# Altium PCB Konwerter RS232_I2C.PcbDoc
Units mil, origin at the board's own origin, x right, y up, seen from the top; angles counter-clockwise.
Board outline 6000 x 4000 mil, 2 copper layers (Top Layer, Bottom Layer); 20 components, 24 nets, 88 pads, 18 vias.
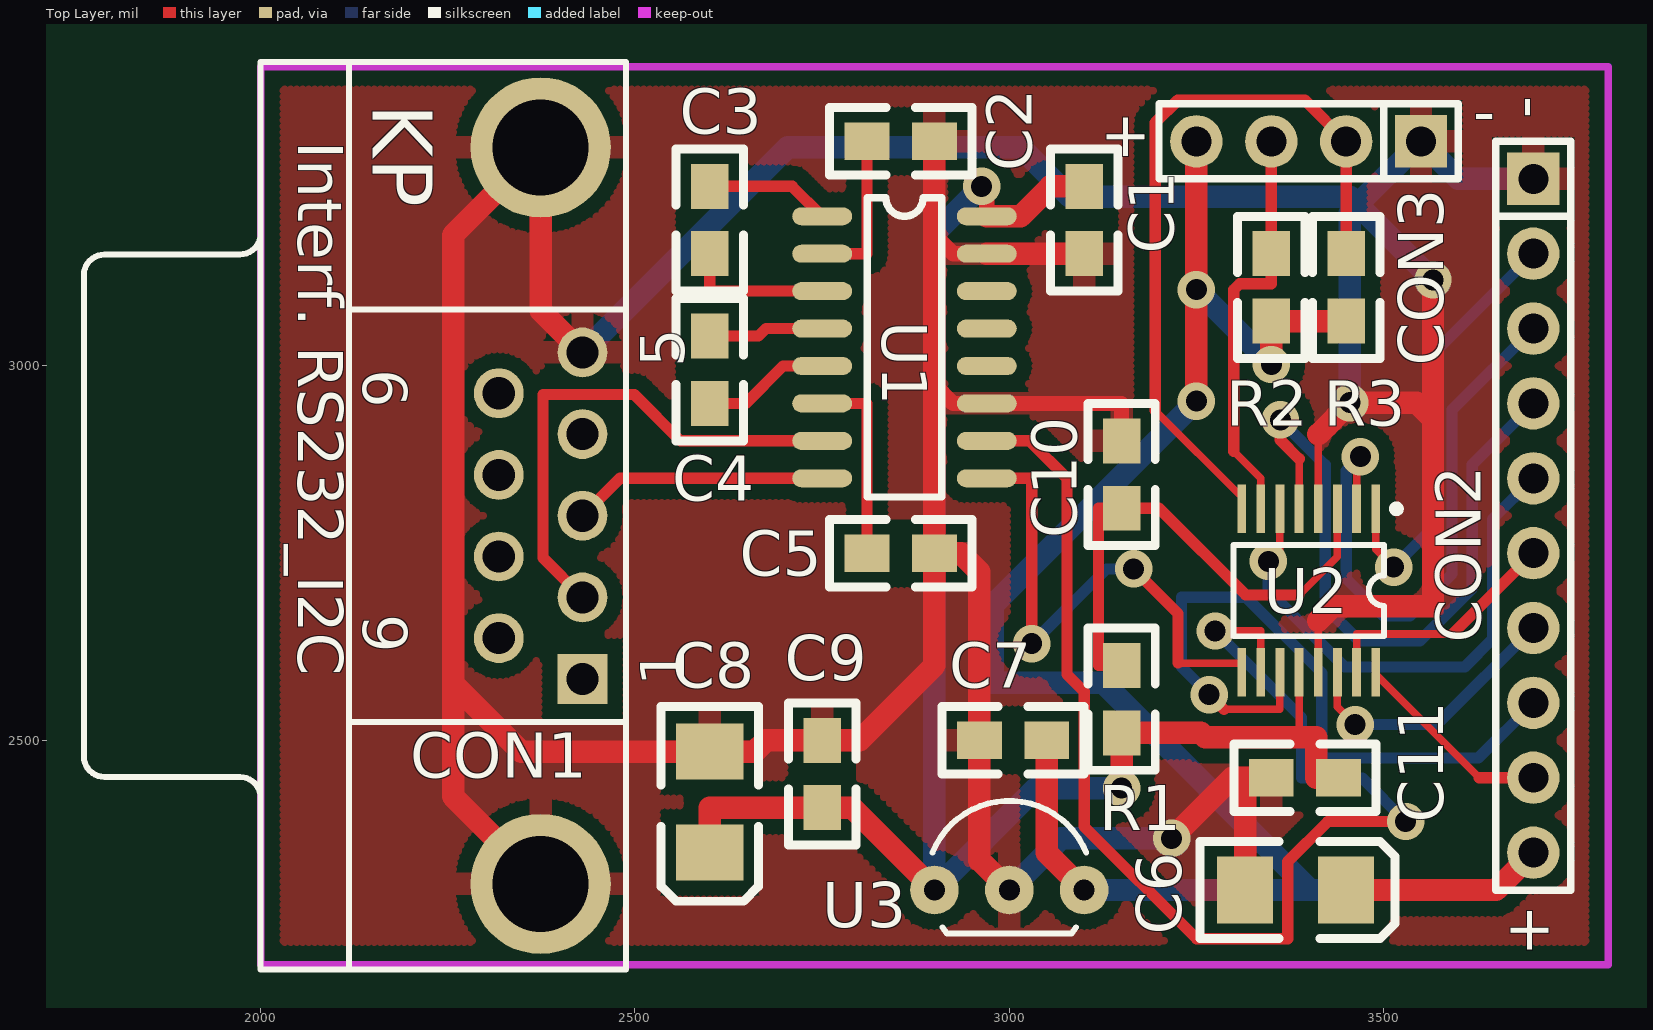
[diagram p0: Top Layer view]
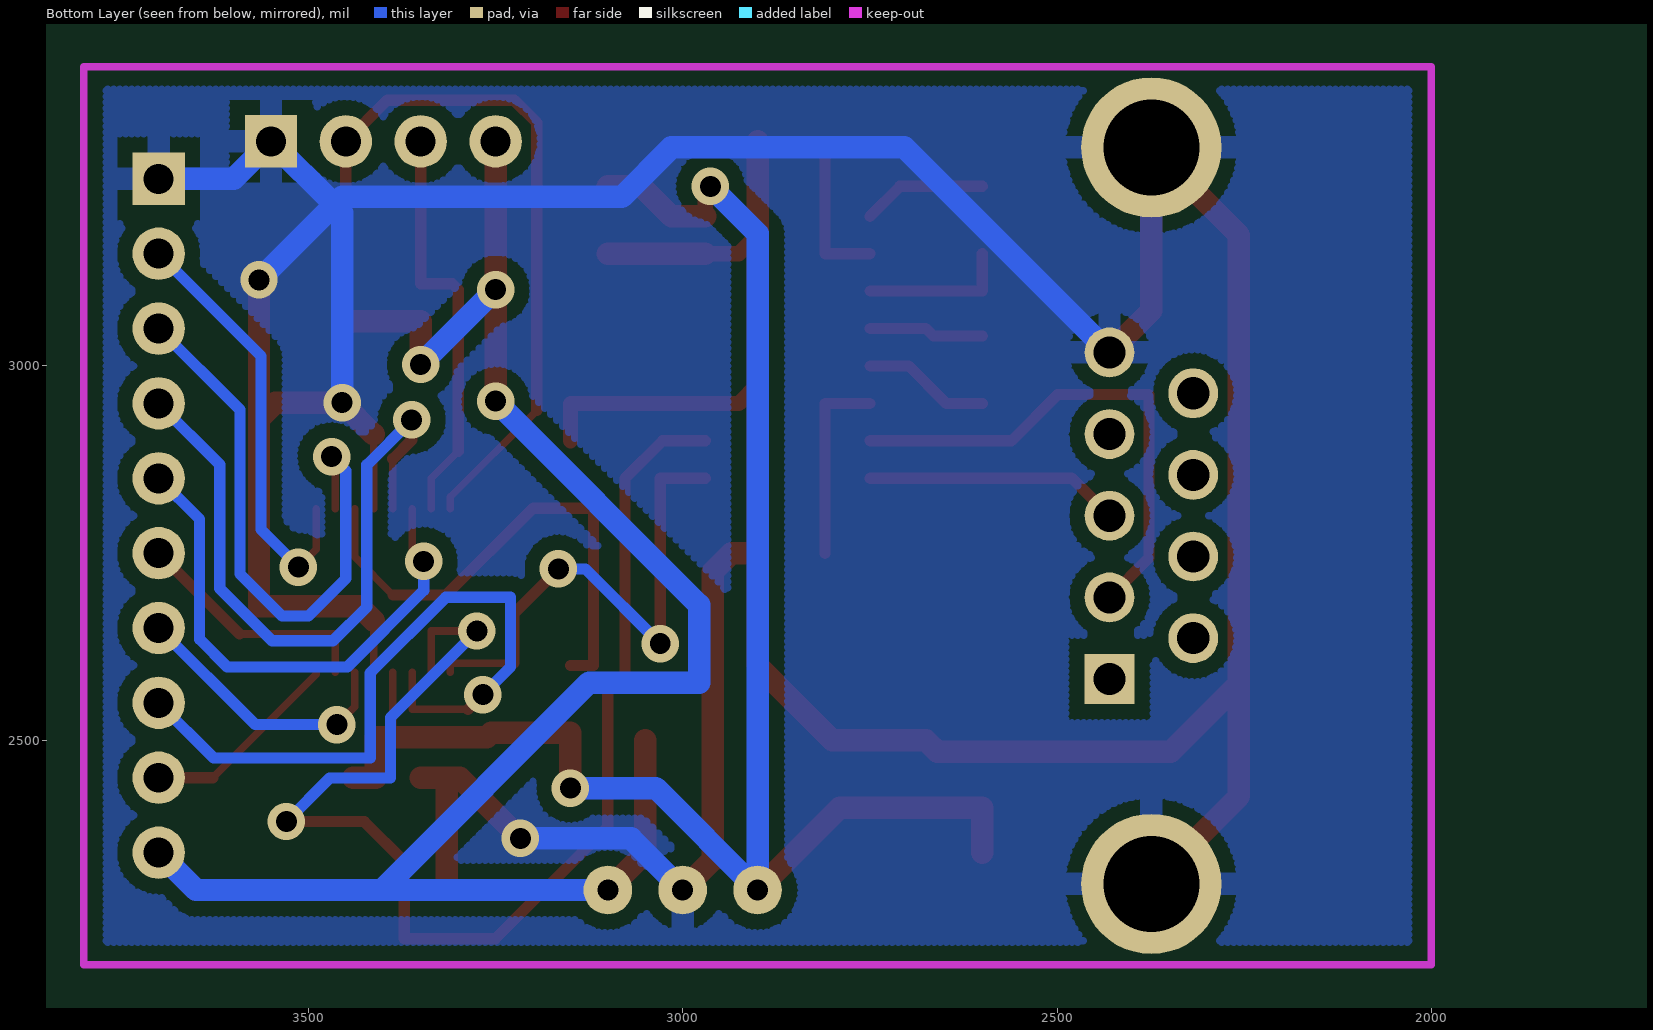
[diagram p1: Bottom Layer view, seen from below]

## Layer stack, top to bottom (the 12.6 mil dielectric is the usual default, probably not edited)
Top Layer: signal copper 1.4
Dielectric: dielectric 12.6, FR-4, Dk 4.8
Bottom Layer: signal copper 1.4

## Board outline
1000,1000 7000,1000 7000,5000 1000,5000

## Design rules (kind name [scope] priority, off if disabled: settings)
Clearance [All] p1: gap=20
ComponentClearance [All] p1: gap=10 collisioncheckmode=3 verticalgap=10
PolygonConnect [All] p1: connectstyle=Relief reliefconductorwidth=30 reliefentries=4 polygonreliefangle="90 Angle"
RoutingVias [All] p1: holewidth=28 width=50 viastyle="Through Hole" minholewidth=28 minwidth=50 maxholewidth=28 maxwidth=50
SMDNeckDown [All] p1: percent=85.000
SolderMaskExpansion [All] p1: expansion=4
TestPointUsage [All] p1: valid=0 allowmultiple=FALSE
Testpoint [All] p1: side=15 testpointundercomponent=TRUE minsize=40 maxsize=100 preferedsize=60 minholesize=0 maxholesize=40 preferedholesize=32 testpointgrid=1 style=1023 order=0123456789
Width Width_1 [InNet('VCC') Or InNet('V_IN') Or InNet('GND')] p1: maxlimit=30 minlimit=30 preferedwidth=30
Width [All] p2: maxlimit=20 minlimit=15 preferedwidth=15
17 further rules are at their usual default settings.

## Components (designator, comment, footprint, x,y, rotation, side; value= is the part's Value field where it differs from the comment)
C1 "Cap" 0805 3100,3150 r90 top
C2 "Cap" 0805 2900,3300 r180 top
C3 "Cap" 0805 2600,3150 r90 top
C4 "Cap" 0805 2600,2950 r90 top
C5 "Cap" 0805 2900,2750 r180 top
C6 "10u" 3528 3450,2300 r0 top
C7 "100n" 0805 3050,2500 r180 top
C8 "10u" 3528 2600,2350 r270 top
C9 "100n" 0805 2750,2500 r270 top
C10 "100n" 0805 3150,2900 r270 top
C11 "100n" 0805 3350,2450 r0 top
CON1 "D Connector 9" DSUB1.385-2H9 2000,2800 r90 top
CON2 "Header 10" sip10 3700,3250 r270 top
CON3 "Header 4" sip-4 3550,3300 r180 top
R1 "10k" 0805 3150,2600 r270 top
R2 "4,7k" 0805 3350,3150 r270 top
R3 "4,7k" 0805 3450,3150 r270 top
U1 "MAX3232CWE" so-16 2750,3200 r0 top
U2 "SC18IM700" TSSO5x6-G16 3400,2700 r180 top
U3 "LM2950" to-92c 2900,2300 r90 top

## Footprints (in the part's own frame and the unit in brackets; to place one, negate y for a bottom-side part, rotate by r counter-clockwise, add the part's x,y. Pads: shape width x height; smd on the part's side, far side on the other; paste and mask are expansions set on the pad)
0805 [mil]
  rect 60x50 smd: 1(0,0) 2(90,0)
  silkscreen extent -50,-45 140,45
3528 [mil]
  rect 75x90 smd: 1(0,0) 2(-135,0)
  silkscreen extent -195,-65 65,65
DSUB1.385-2H9 [mm] "Connector; D Subminiature; 9 Position; Right Angle; Pitch 1.385 mm"
  rect 1.69x1.69 hole 1.09: 1(-5.54,-10.92)
  round 1.69 hole 1.09: 2(-2.77,-10.92) 3(0,-10.92) 4(2.77,-10.92) 5(5.54,-10.92) 6(-4.155,-8.08) 7(-1.385,-8.08) 8(1.385,-8.08) 9(4.155,-8.08)
  round 4.76 hole 3.26: 10(-12.495,-9.5) 11(12.495,-9.5)
  silkscreen extent -15.4,-12.4 15.4,6
sip10 [mil]
  rect 70x70 hole 40 unplated: 1(0,0)
  round 70 hole 40 unplated: 2(100,0) 3(200,0) 4(300,0) 5(400,0) 6(500,0) 7(600,0) 8(700,0) 9(800,0) 10(900,0)
  silkscreen extent -50,-50 950,50
sip-4 [mil]
  rect 70x70 hole 40: 1(0,0)
  round 70 hole 40: 2(100,0) 3(200,0) 4(300,0)
  silkscreen extent -50,-50 350,50
so-16 [mil]
  oval 80x24 smd: 1(0,0) 2(0,-50) 3(0,-100) 4(0,-150) 5(0,-200) 6(0,-250) 7(0,-300) 8(0,-350) 9(220,-350) 10(220,-300) 11(220,-250) 12(220,-200) 13(220,-150) 14(220,-100) 15(220,-50) 16(220,0)
  silkscreen extent 60,-375 160,25
to-92c [mil]
  round 65 hole 28: 1(0,0) 2(0,-100) 3(0,-200)
  silkscreen extent -58,-203 119,3
TSSO5x6-G16 [mm] "Shrink Small Outline; 16 Leads; Body Width 4.4 mm; Pitch 0.65 mm"
  rect 0.3x1.65 smd: 1(-2.275,-2.775) 2(-1.625,-2.775) 3(-0.975,-2.775) 4(-0.325,-2.775) 5(0.325,-2.775) 6(0.975,-2.775) 7(1.625,-2.775) 8(2.275,-2.775) 9(2.275,2.775) 10(1.625,2.775) 11(0.975,2.775) 12(0.325,2.775) 13(-0.325,2.775) 14(-0.975,2.775) 15(-1.625,2.775) 16(-2.275,2.775)
  silkscreen extent -3.1,-2.9 2.55,1.55

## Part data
C1 C2 C3 C4 C5: "Capacitor"
C6 C8: library part ELECTRO1, "Electrolytic Capacitor"
C7 C9 C10 C11: library part CAP, "Capacitor"
CON1: "Receptacle Assembly, 9 Position, Right Angle"
CON2: "Header, 10-Pin"
CON3: "Header, 4-Pin"
R1 R2 R3: library part Res2, "Resistor"
U1: "3.0V TO 5.5V, Low-Power, up to 1Mbps, True RS-232 Transceiver Using Four 0.1µF External Capacitor"
U3: library part "Volt Reg", "Voltage Regulator"

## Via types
v1: diameter 50, hole 28, Top Layer to Bottom Layer, 18 vias

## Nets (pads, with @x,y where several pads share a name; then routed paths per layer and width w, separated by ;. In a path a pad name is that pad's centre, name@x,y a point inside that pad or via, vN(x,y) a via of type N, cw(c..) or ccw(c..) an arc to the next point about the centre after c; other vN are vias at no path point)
GND: C1.1 C2.1 C5.1 C6.2 C7.2 C8.2 C9.1 C10.1 C11.1 CON1.5 CON1.10 CON1.11 CON2.1 CON3.1 U1.11 U1.15 U2.4 U2.13 U3.2 | length 7553.3
  Top Layer w10.04: U2.13 3412.8,2659.8 ; U2.4 3412.8,2908.8
  Top Layer w20.4: C2.1 2900,3175 ; U1.15 2925,3150 2900,3175 ; C10.1 3150,2950 U1.11 2925,2950 2900,2975 2900,3175
  Top Layer w30: CON1.10 2257,2425.09 2257,2576 ; CON1.5 2374.02,3074.02 CON1.11 2257,3174.91 2257,2576 ; C2.1 2900,3175 2900,2975 C5.1 ; U1.15 C1.1 ; U3.2 2960,2340 C7.2 2960,2725 2935,2750 C5.1 ; v1(3217,2369) 3298,2450 3315,2450 ; C6.2 3315,2450 ; C11.1 3315,2450 ; 3412.8,2659.8 3432,2679 3566,2679 3566,2929 ; 3412.8,2908.8 v1(3455,2951) 3544,2951 3566,2929 ; v1(3566,3114.93) 3566,2929 ; 2257,2576 2348,2485 C8.2 2660,2485 2675,2500 C9.1 2800,2500 2900,2600 C5.1
  Bottom Layer w30: CON1.5 2703.81,3292 3015.33,3292 3081.4,3225.93 3455,3225.93 3465.46,3215.46 ; U3.2 3069,2369 v1(3217,2369) ; v1(3455,2951) 3455,3205 3465.46,3215.46 ; v1(3566,3114.93) 3465.46,3215.46 ; CON2.1 3600,3250 CON3.1 3465.46,3215.46
NetC2_2: C2.2 U1.2 | length 210
  Top Layer w15: U1.2 2810,3150 C2.2
NetC3_1: C3.1 U1.3 | length 200
  Top Layer w15: C3.1 2600,3100 U1.3
NetC3_2: C3.2 U1.1 | length 166.6
  Top Layer w15: C3.2 2710,3240 U1.1
NetC4_1: C4.1 U1.5 | length 170.7
  Top Layer w15: C4.1 2648,2950 2698,3000 U1.5
NetC4_2: C4.2 U1.4 | length 154.1
  Top Layer w15: C4.2 2665,3040 2675,3050 U1.4
NetC5_2: C5.2 U1.6 | length 260
  Top Layer w15: U1.6 2810,2950 C5.2
NetC10_2: C10.2 R1.1 U2.3 | length 693.5
  Top Layer w10.04: 3387,2694 3438.39,2745.39 U2.3
  Top Layer w15: R1.1 3119.03,2600 3119.03,2810 C10.2 3200,2810 3316,2694 3387,2694
NetCON1_2: CON1.2 U1.7 | length 691.7
  Top Layer w15: CON1.2 2377,2743.87 2377,2962 2499,2962 2561,2900 U1.7
NetCON1_3: CON1.3 U1.8 | length 340.8
  Top Layer w15: CON1.3 2479.92,2850 U1.8
NetCON2_2: CON2.2 U2.1 | length 583.7
  Top Layer w10.04: U2.1 3489.57,2755.18 v1(3513.37,2731.37)
  Bottom Layer w15: v1(3513.37,2731.37) 3563.5,2781.5 3563.5,3013.5 CON2.2
NetCON2_3: CON2.3 U2.2 | length 800.6
  Top Layer w10.04: U2.2 3463.98,2873.98 v1(3469,2879)
  Bottom Layer w15: v1(3469,2879) 3450,2860 3450,2716.15 3500,2666.15 3535.31,2666.15 3591.5,2722.33 3591.5,2941.5 CON2.3
NetCON2_4: CON2.4 U2.5 | length 928.9
  Top Layer w10.04: U2.5 3387.21,2876
  Top Layer w15: v1(3362,2928) 3362,2901.21 3387.21,2876
  Bottom Layer w15: v1(3362,2928) 3422,2868 3422,2678.14 3467.14,2633 3548.56,2633 3618.5,2702.94 3618.5,2868.5 CON2.4
NetCON2_5: CON2.5 U2.6 | length 710.2
  Top Layer w10.04: v1(3346,2739) 3361.61,2754.61 U2.6
  Bottom Layer w15: v1(3346,2739) 3346,2700.14 3448.14,2598 3608.39,2598 3645.5,2635.11 3645.5,2795.5 CON2.5
NetCON2_6: CON2.6 U2.15 | length 332
  Top Layer w10.04: U2.15 3463.98,2642 3592,2642
  Top Layer w15: 3592,2642 CON2.6
NetCON2_7: CON2.7 U2.14 | length 371
  Top Layer w10.04: U2.14 3438.39,2544.61 v1(3462,2521)
  Bottom Layer w15: v1(3462,2521) 3571,2521 CON2.7
NetCON2_8: CON2.8 U2.11 | length 953.4
  Top Layer w10.04: 3286.75,2541.25 3361.61,2541.25 U2.11
  Top Layer w15: v1(3267,2561) 3286.75,2541.25
  Bottom Layer w15: v1(3267,2561) 3230,2598 3230,2691 3316.5,2691 3417.5,2590 3417.5,2476.5 3626.5,2476.5 CON2.8
NetCON2_9: CON2.9 U2.16 | length 270.3
  Top Layer w10.04: U2.16 3489.57,2588.1 3627.67,2450
  Top Layer w15: 3627.67,2450 CON2.9
NetCON3_2: CON3.2 R3.1 U2.8 | length 1003.8
  Top Layer w10.04: 3195,2940.43 3310.43,2825 U2.8
  Top Layer w15: 3195,2940.43 3195,3325 3225,3355 3395,3355 CON3.2 R3.1
NetCON3_3: CON3.3 R2.1 U2.7 | length 551
  Top Layer w10.04: 3300,2885.98 3336.02,2849.96 U2.7
  Top Layer w15: 3300,2885.98 3300,3102 3308,3110 3350,3110 R2.1 CON3.3
NetU1_9: U1.9 U2.9 | length 706.2
  Top Layer w10.04: 3225.51,2603.21 3310.43,2603.21 U2.9
  Top Layer w15: U1.9 3030,2850 v1(3030,2629) ; v1(3166,2729) 3225.51,2669.49 3225.51,2603.21
  Bottom Layer w15: v1(3030,2629) 3130,2729 v1(3166,2729)
NetU1_10: U1.10 U2.10 | length 1742.7
  Top Layer w10.04: v1(3275,2646) 3336.02,2646 U2.10
  Top Layer w15: U1.10 3027,2900 3077,2850 3077,2588 3100,2565 3100,2385 3250,2235 3372,2235 3372,2338 3425.5,2391.5 v1(3529.5,2391.5)
  Bottom Layer w15: v1(3275,2646) 3390.5,2530.5 3390.5,2449.5 3471.5,2449.5 v1(3529.5,2391.5)
V_IN: C6.1 C7.1 CON2.10 CON3.4 R2.2 R3.2 U3.3 | length 2786
  Top Layer w30: C7.1 3050,2350 U3.3 ; v1(3250,2953) v1(3250,3102) CON3.4 ; v1(3350,3002) R2.2 R3.2 ; C6.1 3650,2300 CON2.10
  Bottom Layer w30: U3.3 3402,2300 ; v1(3250,2953) 2978,2681 2978,2577 3125,2577 3402,2300 ; v1(3250,3102) v1(3350,3002) ; CON2.10 3650,2300 3402,2300
VCC: C1.2 C8.1 C9.2 C11.2 R1.2 U1.16 U2.12 U3.1 | length 2372.4
  Top Layer w10: 3387.21,2506.47 U2.12
  Top Layer w20.4: v1(2963,3240) 2970,3233 U1.16
  Top Layer w30: C8.1 2600,2410 C9.2 2790,2410 U3.1 ; U1.16 3015,3200 3055,3240 C1.2 ; v1(3150,2436) R1.2 3256,2510 3261.73,2504.27 3410.16,2504.27 3410.16,2450 C11.2
  Bottom Layer w30: v1(2963,3240) 2900,3177 U3.1 3036,2436 v1(3150,2436)
pads on no net: CON1.1 CON1.4 CON1.6 CON1.7 CON1.8 CON1.9 U1.12 U1.13 U1.14
copper on no net: | length 3.1
  Top Layer w10: 3385,2504.27 3387.21,2506.47

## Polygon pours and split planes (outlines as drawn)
GND on Top Layer (hatched 90Degree grid 8 track 10, remove dead copper): 2000,3400 3800,3400 3800,2200 2000,2200
GND on Bottom Layer (hatched 90Degree grid 8 track 10, remove dead copper): 2000,3400 3800,3400 3800,2200 2000,2200

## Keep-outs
Keep-Out Layer:
  lines w10: 2000,2200 3800,2200 3800,3400 2000,3400 2000,2200

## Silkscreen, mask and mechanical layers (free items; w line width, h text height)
Top Overlay:
  text "-" at 3670,3360 h60 r270
  text "KP" at 2150,3350 h80 r270
  text "+" at 3130,3340 h60 r270
  text "-" at 3620,3310 h60
  text "Interf. RS232_I2C" at 2050,3300 h60 r270
  text "+" at 3670,2280 h60 r270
